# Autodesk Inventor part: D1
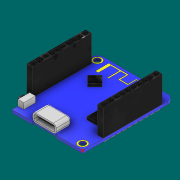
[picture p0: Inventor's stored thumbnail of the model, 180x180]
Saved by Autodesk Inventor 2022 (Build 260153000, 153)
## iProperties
Created: 2021-11
Part Number: D1
Material: Generic
Document SubType Name: Modeling
Designer: santi
Density: 1 g/cm^3
Appearance: Default
Author: santi
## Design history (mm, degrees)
sketch "Sketch1"
  geometry: L1 (0, 0)-(0, -31); L2 (0, -31)-(26, -31); L3 (26, -31)-(26, 0); L4 (26, 0)-(0, 0)
  constraints: 8 end point, 3 perpendicular, 1 vertical
  dimensions: "d0" = 31 distance of L1.start L1.end; "d1" = 26 distance of L1.end L2.end
extrude "Extrusion1" new body sketch "Sketch1" distance "d2" = 1; taper "d3" = 0 deg
fillet "Fillet1" dims "d4" = 2
sketch "Sketch2"
  geometry: L1 (0, 0)-(-2, 0); L2 (-26, 0)-(0, 0) reference; L3 (-2, 0)-(-2, 2); L4 (-26, 29)-(-26, 0) reference; L5 (-26, 29)-(-24, 29); C1 r 1 at (-2, 2); C2 r 1 at (-24, 29)
  constraints: 6 end point, 2 centre point, 2 coincident, 1 horizontal, 1 perpendicular, 1 point on line
  dimensions: "d5" = 2 distance of L1.start L1.end; "d6" = 2 distance of L1.end L3.end; "d7" = 2 diameter of C1; "d8" = 2 distance of L4.start L5.end; "d9" = 2 diameter of C2
extrude "Extrusion2" cut sketch "Sketch2" distance "d10" = 2 (= d7); taper "d11" = 0 deg
sketch "Sketch3"
  geometry: L1 (-26, 0)-(0, 0) reference; L2 (0, 0)-(0, 7); L3 (0, 0)-(0, 29) reference; L4 (0, 7)-(-2, 7); L5 (-2, 7)-(-2, 27); L6 (-2, 27)-(0, 27); L7 (0, 7)-(0, 27); L8 (-13, 0)-(-13, 9.207); L9 (-26, 0)-(-26, 7); L10 (-26, 0)-(-26, 29); L11 (-26, 7)-(-24, 7); L12 (-24, 7)-(-24, 27); L13 (-24, 27)-(-26, 27); L14 (-26, 7)-(-26, 27)
  constraints: 24 end point, 5 symmetric about line, 4 point on line, 3 perpendicular, 2 vertical, 1 midpoint
  dimensions: "d12" = 7 distance of L1.end L2.end; "d13" = 2 distance of L2.end L4.end; "d14" = 20 distance of L4.end L5.end
extrude "Extrusion3" join sketch "Sketch3" distance "d15" = 9; taper "d16" = 0 deg
sketch "Sketch4"
  geometry: L1 (-26, 0)-(0, 0) reference; L2 (-13, 0)-(-13, 5); L3 (-13, 5)-(-9, 5); L4 (-9, 5)-(-9, 0); L5 (-13, 5)-(-17, 5); L6 (-17, 5)-(-17, 0); L7 (-17, 0)-(-9, 0); 1 further point
  constraints: 12 end point, 2 perpendicular, 2 symmetric about line, 1 horizontal, 1 midpoint, 1 point on line, 1 vertical
  dimensions: "d17" = 5 distance of L2.start L2.end; "d18" = 4 distance of L2.end L3.end
extrude "Extrusion4" join sketch "Sketch4" distance "d19" = 3; taper "d20" = 0 deg
fillet "Fillet2" dims "d21" = 1
sketch "Sketch5"
  geometry: L1 (9, 1)-(17, 1) reference; L2 (17, 1)-(9, 1); L3 (9, 1)-(11, 1); L4 (9, 1)-(10, 1); L5 (9, 1)-(9, 3) reference; L6 (13, 1)-(13, 2.179); L7 (17, 1)-(16, 1); L8 (17, 1)-(17, 3); A1 r 1 centre (10, 2) between (9, 2) and (10, 1); A2 r 1 centre (16, 2) between (16, 1) and (17, 2); 3 further points
  constraints: 12 end point, 4 point on circle, 4 symmetric about line, 3 midpoint, 2 centre point, 1 collinear, 1 point on line, 1 tangent, 1 vertical, 1 other
  dimensions: "d23" = 1 distance of L1.start L4.end
extrude "Extrusion5" cut sketch "Sketch5" distance "d24" = 5; taper "d25" = 0 deg
sketch "Sketch6"
  geometry: L1 (-26, 7)-(-24, 7) reference; L2 (-26, 7)-(-26, 0) reference; L3 (-24, 7)-(-24, 0); L4 (-26, 0)-(0, 0) reference; L5 (-26, 0)-(-24, 0)
  constraints: 4 end point, 1 collinear, 1 point on line, 1 vertical
extrude "Extrusion6" cut sketch "Sketch6" distance "d26" = 5; taper "d27" = 0 deg
sketch "Sketch7"
  geometry: L1 (-24, 0)-(-16, 0) reference; L2 (-24, 0)-(-24, 2); L3 (-24, 7)-(-24, 0) reference; L4 (-24, 2)-(-22, 2); L5 (-22, 2)-(-22, 6); L6 (-22, 6)-(-24, 6); L7 (-24, 2)-(-24, 6); 1 further point
  constraints: 10 end point, 3 perpendicular, 2 point on line, 1 collinear
  dimensions: "d28" = 2 distance of L1.start L2.end; "d29" = 2 distance of L2.end L4.end; "d30" = 4 distance of L4.end L5.end
extrude "Extrusion7" join sketch "Sketch7" distance "d31" = 2; taper "d32" = 0 deg
sketch "Sketch8"
  geometry: L1 (-2, 3)-(-6, 3) reference; L2 (-4, 3)-(-4, 1); L3 (0, 1)-(-5, 1) reference; L4 (-5, 2)-(0, 2) reference; L5 (-4, 2)-(-3, 2); L6 (-3, 2)-(-5, 2); L7 (-5, 2)-(-5, 2.5); L8 (-5, 2)-(-5, 3) reference; L9 (-5, 2.5)-(-3, 2.5); L10 (-3, 2.5)-(-3, 1.5); L11 (-3, 1.5)-(-5, 1.5); L12 (-5, 2)-(-5, 1) reference; L13 (-5, 2)-(-5, 1.5); 1 further point
  constraints: 16 end point, 4 midpoint, 3 point on line, 2 perpendicular, 1 collinear, 1 vertical
  dimensions: "d33" = 1 distance of L5.start L5.end; "d34" = 0.5 distance of L4.start L7.end (derived); "d35" = 1 distance of L9.end L10.end
extrude "Extrusion8" join sketch "Sketch8" distance "d36" = 1; taper "d37" = 0 deg
sketch "Sketch9"
  geometry: L1 (-24, 27)-(-26, 27) reference; L2 (-26, 27)-(-26, 7) reference; L3 (-26, 7)-(-24, 7) reference; L4 (-24, 7)-(-24, 27) reference; L5 (-25.7, 26.7)-(-24.3, 26.7); L6 (-24.3, 25.1)-(-24.3, 7.3); L7 (-24.3, 7.3)-(-25.7, 7.3); L8 (-25.7, 7.3)-(-25.7, 26.7); L9 (-24.3, 26.7)-(-24.3, 25.1); L10 (-24.3, 25.1)-(-25.7, 25.1); L11 (-25.7, 24.8)-(-24.3, 24.8); L12 (-24, 24.9)-(-24, 26.7); L13 (-25.7, 23.2)-(-24.3, 23.2); L14 (-25.7, 22.9)-(-24.3, 22.9); L15 (-25.7, 21.3)-(-24.3, 21.3); L16 (-25.7, 21)-(-24.3, 21); L17 (-25.7, 19.4)-(-24.3, 19.4); L18 (-25.7, 19.1)-(-24.3, 19.1); L19 (-25.7, 17.5)-(-24.3, 17.5); L20 (-25.7, 17.2)-(-24.3, 17.2); L21 (-25.7, 15.6)-(-24.3, 15.6); L22 (-25.7, 15.3)-(-24.3, 15.3); L23 (-25.7, 13.7)-(-24.3, 13.7); L24 (-25.7, 13.4)-(-24.3, 13.4); L25 (-25.7, 11.8)-(-24.3, 11.8); L26 (-25.7, 11.5)-(-24.3, 11.5); L27 (-25.7, 9.9)-(-24.3, 9.9); L28 (-25.7, 9.5)-(-24.3, 9.5); 34 further points
  constraints: 48 end point, 16 parallel, 2 point on line, 1 perpendicular, 1 other
  dimensions: "d38" = 0.3 distance between parallel lines of L1 L5; "d39" = 1.6 distance of L6.start L5.end; "d40" = 0.3 distance between parallel lines of L10 L11; "d41" = 1.6 distance between parallel lines of L11 L13; "d42" = 0.3 distance between parallel lines of L13 L14; "d43" = 1.6 distance between parallel lines of L14 L15; "d44" = 0.3 distance between parallel lines of L15 L16; "d45" = 1.6 distance between parallel lines of L16 L17; "d46" = 0.3 distance between parallel lines of L17 L18; "d47" = 1.6 distance between parallel lines of L18 L19; "d48" = 0.3 distance between parallel lines of L19 L20; "d49" = 1.6 distance between parallel lines of L20 L21; "d50" = 0.3 distance between parallel lines of L21 L22; "d51" = 1.6 distance between parallel lines of L22 L23; "d52" = 0.3 distance between parallel lines of L23 L24; "d53" = 1.6 distance between parallel lines of L24 L25; "d54" = 0.3 distance between parallel lines of L25 L26; "d55" = 1.6 distance between parallel lines of L26 L27; "d56" = 0.4 distance between parallel lines of L27 L28
extrude "Extrusion9" cut sketch "Sketch9" distance "d57" = 9; taper "d58" = 0 deg
sketch "Sketch10"
  geometry: L1 (-25.7, 13.4)-(-24.3, 13.4) reference; L2 (-24.3, 13.4)-(-24.3, 11.8) reference; L3 (-24.3, 11.8)-(-25.7, 11.8) reference; L4 (-25.7, 11.8)-(-25.7, 13.4) reference; L5 (-25.7, 21)-(-24.3, 21) reference; L6 (-24.3, 21)-(-24.3, 19.4) reference; L7 (-24.3, 19.4)-(-25.7, 19.4) reference; L8 (-25.7, 19.4)-(-25.7, 21) reference; L9 (-25.7, 25.1)-(-25.7, 26.7) reference; L10 (-25.7, 26.7)-(-24.3, 26.7) reference; L11 (-24.3, 26.7)-(-24.3, 25.1) reference; L12 (-24.3, 25.1)-(-25.7, 25.1) reference; L13 (-25.7, 19.1)-(-24.3, 19.1) reference; L14 (-24.3, 19.1)-(-24.3, 17.5) reference; L15 (-24.3, 17.5)-(-25.7, 17.5) reference; L16 (-25.7, 17.5)-(-25.7, 19.1) reference; L17 (-25.7, 11.5)-(-24.3, 11.5) reference; L18 (-24.3, 11.5)-(-24.3, 9.9) reference; L19 (-24.3, 9.9)-(-25.7, 9.9) reference; L20 (-25.7, 9.9)-(-25.7, 11.5) reference; L21 (-25.7, 15.3)-(-24.3, 15.3) reference; L22 (-24.3, 15.3)-(-24.3, 13.7) reference; L23 (-24.3, 13.7)-(-25.7, 13.7) reference; L24 (-25.7, 13.7)-(-25.7, 15.3) reference; L25 (-25.7, 22.9)-(-24.3, 22.9) reference; L26 (-24.3, 22.9)-(-24.3, 21.3) reference; L27 (-24.3, 21.3)-(-25.7, 21.3) reference; L28 (-25.7, 21.3)-(-25.7, 22.9) reference; L29 (-25.7, 24.8)-(-24.3, 24.8) reference; L30 (-24.3, 24.8)-(-24.3, 23.2) reference; L31 (-24.3, 23.2)-(-25.7, 23.2) reference; L32 (-25.7, 23.2)-(-25.7, 24.8) reference; L33 (-25.7, 17.2)-(-24.3, 17.2) reference; L34 (-24.3, 17.2)-(-24.3, 15.6) reference; L35 (-24.3, 15.6)-(-25.7, 15.6) reference; L36 (-25.7, 15.6)-(-25.7, 17.2) reference; L37 (-25.7, 9.5)-(-24.3, 9.5) reference; L38 (-24.3, 9.5)-(-24.3, 7.3) reference; L39 (-24.3, 7.3)-(-25.7, 7.3) reference; L40 (-25.7, 7.3)-(-25.7, 9.5) reference; L41 (-24, 27)-(-26, 27) reference; L42 (-26, 27)-(-26, 7) reference; L43 (-26, 7)-(-24, 7) reference; L44 (-24, 7)-(-24, 27) reference; L45 (-2, 31)-(-24, 31) reference; L46 (-13, 31)-(-13, 22.1); L47 (-1.7, 24.8)-(-1.7, 23.2); L48 (-2, 7)-(-2, 27); L49 (0, 27)-(0, 7); L50 (-1.7, 21)-(-1.7, 19.4); L51 (-0.3, 19.4)-(-0.3, 21); L52 (-0.3, 21)-(-1.7, 21); L53 (-1.7, 21.3)-(-0.3, 21.3); L54 (-1.7, 22.9)-(-1.7, 21.3); L55 (-0.3, 22.9)-(-1.7, 22.9); L56 (-0.3, 21.3)-(-0.3, 22.9); L57 (-1.7, 23.2)-(-0.3, 23.2); L58 (-0.3, 23.2)-(-0.3, 24.8); L59 (-1.7, 25.1)-(-0.3, 25.1); L60 (-2, 27)-(0, 27); L61 (-1.7, 13.4)-(-1.7, 11.8); L62 (-0.3, 11.8)-(-0.3, 13.4); L63 (-1.7, 11.8)-(-0.3, 11.8); L64 (-0.3, 13.4)-(-1.7, 13.4)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; 1 further point
  constraints: 90 end point, 44 symmetric about line, 1 midpoint, 1 vertical
extrude "Extrusion10" cut sketch "Sketch10" distance "d59" = 9; taper "d60" = 0 deg
sketch "Sketch11"
  geometry: C1 r 1 at (-24, 29) reference; C2 r 1.5 at (-24, 29); C3 r 1 at (-2, 2) reference; C4 r 1.5 at (-2, 2); 1 further point
  constraints: 2 centre point
  dimensions: "d61" = 0.5 radial gap between concentric circles of C1 C2; "d62" = 0.5 radial gap between concentric circles of C3 C4
extrude "Extrusion11" join sketch "Sketch11" distance "d63" = 0.01; taper "d64" = 0 deg
sketch "Sketch12"
  geometry: 1 further point
sketch "Sketch13"
  geometry: L1 (-1.7, -22.9)-(-0.3, -22.9) reference; L2 (-0.3, -22.9)-(-0.3, -21.3) reference; L3 (-0.3, -21.3)-(-1.7, -21.3) reference; L4 (-1.7, -21.3)-(-1.7, -22.9) reference; L5 (-0.3, -13.7)-(-1.7, -13.7) reference; L6 (-1.7, -13.7)-(-1.7, -15.3) reference; L7 (-1.7, -15.3)-(-0.3, -15.3) reference; L8 (-0.3, -15.3)-(-0.3, -13.7) reference; L9 (-0.3, -7.3)-(-1.7, -7.3) reference; L10 (-1.7, -7.3)-(-1.7, -9.5) reference; L11 (-1.7, -9.5)-(-0.3, -9.5) reference; L12 (-0.3, -9.5)-(-0.3, -7.3) reference; L13 (-0.3, -15.6)-(-1.7, -15.6) reference; L14 (-1.7, -15.6)-(-1.7, -17.2) reference; L15 (-1.7, -17.2)-(-0.3, -17.2) reference; L16 (-0.3, -17.2)-(-0.3, -15.6) reference; L17 (-0.3, -24.8)-(-0.3, -23.2) reference; L18 (-0.3, -23.2)-(-1.7, -23.2) reference; L19 (-1.7, -23.2)-(-1.7, -24.8) reference; L20 (-1.7, -24.8)-(-0.3, -24.8) reference; L21 (-0.3, -21)-(-0.3, -19.4) reference; L22 (-0.3, -19.4)-(-1.7, -19.4) reference; L23 (-1.7, -19.4)-(-1.7, -21) reference; L24 (-1.7, -21)-(-0.3, -21) reference; L25 (-0.3, -13.4)-(-0.3, -11.8) reference; L26 (-0.3, -11.8)-(-1.7, -11.8) reference; L27 (-1.7, -11.8)-(-1.7, -13.4) reference; L28 (-1.7, -13.4)-(-0.3, -13.4) reference; L29 (-0.3, -9.9)-(-1.7, -9.9) reference; L30 (-1.7, -9.9)-(-1.7, -11.5) reference; L31 (-1.7, -11.5)-(-0.3, -11.5) reference; L32 (-0.3, -11.5)-(-0.3, -9.9) reference; L33 (-0.3, -17.5)-(-1.7, -17.5) reference; L34 (-1.7, -17.5)-(-1.7, -19.1) reference; L35 (-1.7, -19.1)-(-0.3, -19.1) reference; L36 (-0.3, -19.1)-(-0.3, -17.5) reference; L37 (-1.7, -26.7)-(-0.3, -26.7) reference; L38 (-0.3, -26.7)-(-0.3, -25.1) reference; L39 (-0.3, -25.1)-(-1.7, -25.1) reference; L40 (-1.7, -25.1)-(-1.7, -26.7) reference; L41 (-2, -7)-(0, -7) reference; L42 (0, -7)-(0, -27) reference; L43 (0, -27)-(-2, -27) reference; L44 (-2, -27)-(-2, -7) reference; L45 (-25.7, -13.4)-(-24.3, -13.4) reference; L46 (-24.3, -13.4)-(-24.3, -11.8) reference; L47 (-24.3, -11.8)-(-25.7, -11.8) reference; L48 (-25.7, -11.8)-(-25.7, -13.4) reference; L49 (-25.7, -21)-(-24.3, -21) reference; L50 (-24.3, -21)-(-24.3, -19.4) reference; L51 (-24.3, -19.4)-(-25.7, -19.4) reference; L52 (-25.7, -19.4)-(-25.7, -21) reference; L53 (-25.7, -25.1)-(-25.7, -26.7) reference; L54 (-25.7, -26.7)-(-24.3, -26.7) reference; L55 (-24.3, -26.7)-(-24.3, -25.1) reference; L56 (-24.3, -25.1)-(-25.7, -25.1) reference; L57 (-25.7, -19.1)-(-24.3, -19.1) reference; L58 (-24.3, -19.1)-(-24.3, -17.5) reference; L59 (-24.3, -17.5)-(-25.7, -17.5) reference; L60 (-25.7, -17.5)-(-25.7, -19.1) reference; L61 (-25.7, -11.5)-(-24.3, -11.5) reference; L62 (-24.3, -11.5)-(-24.3, -9.9) reference; L63 (-24.3, -9.9)-(-25.7, -9.9) reference; L64 (-25.7, -9.9)-(-25.7, -11.5) reference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; 1 further point
extrude "Extrusion12" join sketch "Sketch13" distance "d65" = 1; taper "d66" = 0 deg
chamfer "Chamfer1" distance "d67" = 0.5; stored, may be unused: second distance "d68" = 2, angle "d69" = 45 deg
chamfer "Chamfer2" distance "d70" = 0.5; stored, may be unused: second distance "d71" = 2, angle "d72" = 45 deg
sketch "Sketch14"
  geometry: C1 r 1.5 at (-2, -2) reference; C2 r 1 at (-2, -2) reference; C3 r 1.5 at (-24, -29) reference; C4 r 1 at (-24, -29) reference; 1 further point
extrude "Extrusion13" join sketch "Sketch14" distance "d73" = 0.01; taper "d74" = 0 deg
sketch "Sketch15"
  geometry: L1 (-24, -7)-(-21, -7); L2 (-21, -7)-(-17, -7); L3 (-17, -7)-(-17, -17); L4 (-17, -17)-(-21, -17); L5 (-21, -17)-(-21, -7); 1 further point
  constraints: 10 end point, 2 perpendicular, 1 horizontal, 1 point on line
  dimensions: "d75" = 3 distance of L1.start L1.end; "d76" = 4 distance of L1.end L2.end; "d77" = 10 distance of L2.end L3.end; "d78" = 4 distance of L3.end L4.end
extrude "Extrusion14" join sketch "Sketch15" distance "d79" = 1; taper "d80" = 0 deg
sketch "Sketch16"
  geometry: L1 (29, 1)-(29, 0) reference; L2 (27, 1)-(29, 1) reference; L3 (27, 1)-(27, 10) reference; L4 (7, 10)-(27, 10) reference; L5 (7, 1)-(7, 10) reference; L6 (0, 1)-(7, 1) reference; L7 (0, 0)-(0, 1) reference; L8 (0, 0)-(29, 0) reference; L9 (7, 1)-(27, 1) reference; L10 (27, 1)-(7, 1); 1 further point
  constraints: 2 end point, 1 collinear
extrude "Extrusion15" join sketch "Sketch16" distance "d81" = 0.01; taper "d82" = 0 deg
sketch "Sketch17"
  geometry: L1 (3.9, 10)-(3.9, 1) reference; L2 (22, 0)-(22, 10) reference; L3 (2, 10)-(22, 10) reference; L4 (2, 1)-(2, 10) reference; L5 (0, 1)-(2, 1) reference; L6 (0, 0)-(0, 1) reference; L7 (0, 0)-(22, 0) reference; L8 (22, 1)-(2, 1) reference; L9 (2, 1)-(22, 1); 1 further point
  constraints: 2 end point, 1 perpendicular
extrude "Extrusion16" join sketch "Sketch17" distance "d83" = 0.01; taper "d84" = 0 deg
sketch "Sketch18"
  geometry: L1 (-1, -2)-(-1, -1) reference; L2 (0, 0)-(6, 0) reference; L3 (7, -2)-(7, -1) reference; L4 (6.5, -2)-(6.5, -1); L5 (6, -0.5)-(0, -0.5); L6 (-0.5, -1)-(-0.5, -2); L7 (6, -2.5)-(0, -2.5); A1 r 1 centre (0, -1) between (0, 0) and (-1, -1) reference; A2 r 1 centre (0, -2) between (-1, -2) and (0, -3) reference; A3 r 1 centre (6, -1) between (7, -1) and (6, 0) reference; A4 r 1 centre (6, -2) between (6, -3) and (7, -2) reference; A5 r 0.5 centre (6, -2) between (6, -2.5) and (6.5, -2); A6 r 0.5 centre (6, -1) between (6.5, -1) and (6, -0.5); A7 r 0.5 centre (0, -1) between (0, -0.5) and (-0.5, -1); A8 r 0.5 centre (0, -2) between (-0.5, -2) and (0, -2.5); 1 further point
  constraints: 8 end point, 8 point on circle, 4 centre point, 1 horizontal, 6 other
  dimensions: "d85" = 0.5 distance between parallel lines of L2 L5
extrude "Extrusion17" cut sketch "Sketch18" distance "d86" = 4; taper "d87" = 0 deg
fillet "Fillet3" dims "d88" = 0.5
sketch "Sketch19"
  geometry: L1 (6.5, -1)-(6.5, -2) reference; L2 (0, -0.5)-(6, -0.5) reference; L3 (-0.5, -2)-(-0.5, -1) reference; L4 (6, -2.5)-(0, -2.5) reference; L5 (5.9, -1.1)-(5.9, -1.9); L6 (5.9, -1.9)-(0.1, -1.9); L7 (0.1, -1.9)-(0.1, -1.1); L8 (0.1, -1.1)-(5.9, -1.1); A1 r 0.5 centre (6, -1) between (6.5, -1) and (6, -0.5) reference; A2 r 0.5 centre (0, -1) between (0, -0.5) and (-0.5, -1) reference; A3 r 0.5 centre (0, -2) between (-0.5, -2) and (0, -2.5) reference; A4 r 0.5 centre (6, -2) between (6, -2.5) and (6.5, -2) reference; 1 further point
  constraints: 8 end point, 3 other
  dimensions: "d89" = 0.6 distance between parallel lines of L2 L8
extrude "Extrusion18" join sketch "Sketch19" distance "d90" = 3; taper "d91" = 0 deg
sketch "Sketch20"
  geometry: L1 (-3.262, 9.702)-(-3.262, 13.702); L2 (-3.262, 13.702)-(-8.262, 13.702); L3 (-8.262, 13.702)-(-8.262, 9.702); L4 (-8.262, 9.702)-(-3.262, 9.702); L5 (-17.843, 24.471)-(-17.843, 19.471); L6 (-17.843, 21.971)-(-15.343, 21.971); L7 (-15.343, 21.971)-(-20.343, 21.971); L8 (-20.343, 21.971)-(-17.843, 24.471); L9 (-15.343, 21.971)-(-17.843, 19.471); L10 (-17.843, 24.471)-(-15.343, 21.971); L11 (-17.843, 19.471)-(-20.343, 21.971); 1 further point
  constraints: 22 end point, 3 perpendicular, 2 vertical, 1 horizontal, 1 midpoint, 1 point on line
  dimensions: "d92" = 4 distance of L1.start L1.end; "d93" = 5 distance of L1.end L2.end; "d94" = 5 distance of L5.start L5.end; "d95" = 2.5 distance of L6.start L6.end; "d96" = 5 distance of L6.end L7.end
extrude "Extrusion19" join sketch "Sketch20" distance "d97" = 1; taper "d98" = 0 deg
sketch "Sketch21"
  geometry: L1 (-4.735, 26.626)-(-4.735, 30.08); L2 (-4.735, 30.08)-(-7.714, 30.08); L3 (-7.714, 30.08)-(-7.714, 27.233); L4 (-7.714, 27.233)-(-9.691, 27.233); L5 (-9.691, 27.233)-(-9.691, 30.08); L6 (-9.691, 30.08)-(-11.853, 30.08); L7 (-11.853, 30.08)-(-11.853, 27.233); L8 (-11.853, 27.233)-(-14.411, 27.233); L9 (-14.411, 27.233)-(-14.411, 30.08); L10 (-14.411, 30.08)-(-17.179, 30.08); L11 (-17.179, 30.08)-(-17.179, 25.492); L12 (-17.179, 25.492)-(-16.751, 25.492); L13 (-16.751, 25.492)-(-16.751, 29.669); L14 (-16.751, 29.669)-(-14.813, 29.669); L15 (-14.813, 29.669)-(-14.813, 26.85); L16 (-14.813, 26.85)-(-11.518, 26.85); L17 (-11.518, 26.85)-(-11.518, 29.818); L18 (-11.518, 29.818)-(-9.98, 29.818); L19 (-9.98, 29.818)-(-9.98, 26.85); L20 (-9.98, 26.85)-(-7.414, 26.85); L21 (-7.414, 26.85)-(-7.414, 29.818); L22 (-7.414, 29.818)-(-5.017, 29.818); L23 (-5.017, 29.818)-(-5.017, 26.121); L24 (-5.017, 26.121)-(-4.735, 26.121); L25 (-4.735, 26.121)-(-4.735, 26.626); L26 (-17.179, 30.08)-(-20.174, 30.08); L27 (-20.174, 30.08)-(-20.174, 25.492); L28 (-20.174, 25.492)-(-21.187, 25.492); L29 (-21.187, 25.492)-(-21.187, 30.08); L30 (-21.187, 30.08)-(-20.174, 30.08); L31 (-17.179, 29.669)-(-20.174, 29.669); 1 further point
  constraints: 62 end point, 24 perpendicular, 14 point on line, 1 horizontal, 1 vertical
extrude "Extrusion20" join sketch "Sketch21" distance "d99" = 0.01; taper "d100" = 0 deg
sketch "Sketch22"
  geometry: L1 (6.5, -1)-(6.5, -2) reference; L2 (6, -2.5)-(0, -2.5) reference; L3 (-0.5, -2)-(-0.5, -1) reference; L4 (0, -0.5)-(6, -0.5) reference; L5 (-8, -3)-(-8, -4) reference; L6 (-8, -4)-(16.01, -4) reference; L7 (16.01, -3)-(16.01, -4) reference; L8 (6, -3)-(16.01, -3) reference; L9 (7, -2)-(7, -1) reference; L10 (0, 0)-(6, 0) reference; L11 (-1, -2)-(-1, -1) reference; L12 (-8, -3)-(0, -3) reference; L13 (8.286, -2.99)-(6.309, -2.99) reference; L14 (7, -2.99)-(7, -4); L15 (-8, -4)-(16.01, -4) reference; L16 (-1.179, -2.99)-(-0.751, -2.99) reference; L17 (-5, -4)-(-1, -4) reference; L18 (-1, -2.99)-(-1, -4); L19 (7, -2.99)-(-1, -2.99); L20 (-1, -4)-(7, -4); A1 r 0.5 centre (6, -1) between (6.5, -1) and (6, -0.5) reference; A2 r 0.5 centre (6, -2) between (6, -2.5) and (6.5, -2) reference; A3 r 0.5 centre (0, -2) between (-0.5, -2) and (0, -2.5) reference; A4 r 0.5 centre (0, -1) between (0, -0.5) and (-0.5, -1) reference; A5 r 1 centre (6, -2) between (6, -3) and (7, -2) reference; A6 r 1 centre (6, -1) between (7, -1) and (6, 0) reference; A7 r 1 centre (0, -1) between (0, 0) and (-1, -1) reference; A8 r 1 centre (0, -2) between (-1, -2) and (0, -3) reference; 6 further points
  constraints: 8 end point, 3 point on line, 2 vertical, 1 horizontal, 1 parallel
extrude "Extrusion21" cut sketch "Sketch22" distance "d101" = 0.5; taper "d102" = 0 deg
sketch "Sketch23"
  geometry: L1 (-5, 1.5)-(-5, 2.5) reference; L2 (-5, 2.5)-(-3, 2.5) reference; L3 (-3, 2.5)-(-3, 1.5) reference; L4 (-3, 1.5)-(-5, 1.5) reference; L5 (0, 0)-(-7, 0) reference; L6 (0, 1)-(0, 0) reference; L7 (-2, 1)-(0, 1) reference; L8 (-2, 1)-(-2, 3) reference; L9 (-6, 3)-(-2, 3) reference; L10 (-6, 1)-(-6, 3) reference; L11 (-7, 1)-(-6, 1) reference; L12 (-7, 1)-(-7, 0) reference; L13 (-6, 1)-(-6, 3) reference; L14 (-6, 1)-(-2, 1); 1 further point
  constraints: 2 end point, 1 perpendicular
extrude "Extrusion22" join sketch "Sketch23" distance "d103" = 0.01; taper "d104" = 0 deg
body "Solid1"
node "Projected Loop1"
node "Projected Loop2"
node "Projected Loop3"
node "Projected Loop4"
node "Projected Loop5"
node "Projected Loop6"
node "Projected Loop7"
node "Projected Loop8"
node "Projected Loop9"
